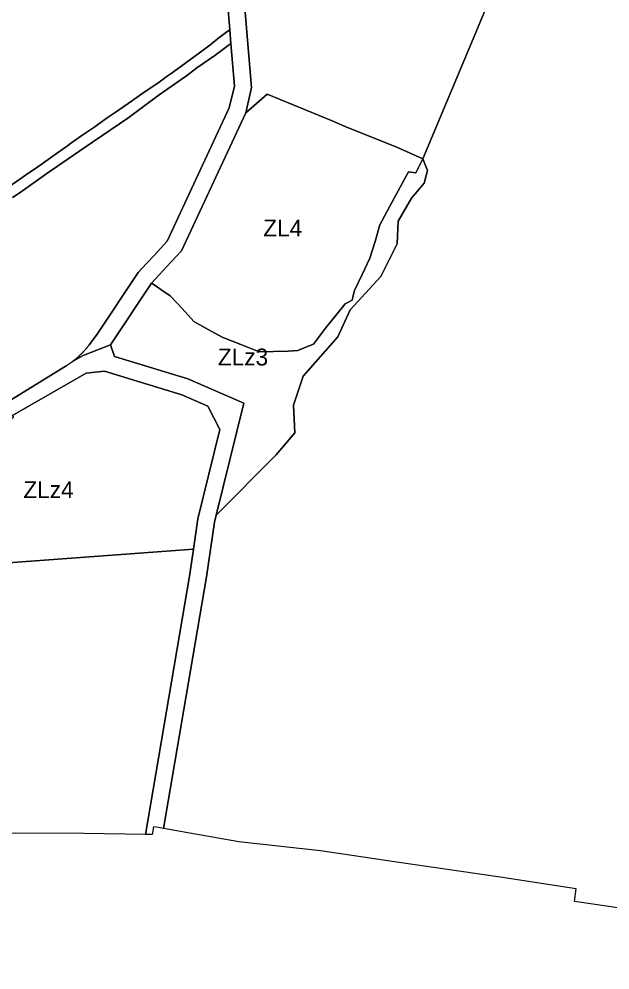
# Model space of a CAD drawing. Extents: x 7439486 to 7443435, y 5551288 to 5554556.
# Drawn here: x 7441389 to 7441738, y 5552052 to 5552613 of the extents above; entities that cross this region are included whole.
import ezdxf

# ---------------------------------------------------------------- set-up
doc = ezdxf.new("R2010")
doc.units = 0
doc.layers.add('linie_rozgraniczajace', color=7, linetype='Continuous')
doc.layers.add('oznaczenia_przeznaczen', color=7, linetype='Continuous')

msp = doc.modelspace()

# ---------------------------------------------------------------- linework, layer by layer
at = {"layer": 'linie_rozgraniczajace'}
for points in [[(7441632.49, 5552909.09), (7441605.42, 5552850.4), (7441542.65, 5552745.21), (7441531.72, 5552727.75), (7441527.41, 5552715.36), (7441523.69, 5552674.78), (7441520.39, 5552638.69), (7441525.97, 5552572.89), (7441522.44, 5552558.06), (7441484.47, 5552476.5), (7441475.68, 5552466.97), (7441471.28, 5552462.21), (7441466.88, 5552457.45)], [(7441473.89, 5552135.18), (7441499.22, 5552283.92), (7441504.07, 5552316.14), (7441505.1, 5552320.35), (7441540.55, 5552355.88), (7441551.52, 5552368.86), (7441550.62, 5552385.33), (7441556.44, 5552402.45), (7441576.8, 5552425.65), (7441584.14, 5552441.59), (7441602.31, 5552461.23), (7441611.94, 5552480.61), (7441612.56, 5552494.07), (7441620.35, 5552507.59), (7441627.86, 5552516.46), (7441629.87, 5552523.95), (7441627.21, 5552530.83), (7441656.87, 5552601.68), (7441668.96, 5552630.65), (7441733.17, 5552791.22), (7441747.99, 5552826)], [(7441510.43, 5552637.85), (7441513.04, 5552607.04), (7441510.55, 5552605.2), (7441505.84, 5552601.59), (7441504.12, 5552600.32), (7441500.41, 5552597.45), (7441495.18, 5552593.48), (7441481.86, 5552583.7), (7441478.5, 5552581.3), (7441476.09, 5552579.58), (7441471.38, 5552576.08), (7441464.62, 5552571.59), (7441462.49, 5552570.18), (7441459.66, 5552568.19), (7441458.28, 5552567.21), (7441453.05, 5552563.53), (7441445.23, 5552558.12), (7441440.65, 5552554.95), (7441435.59, 5552551.46), (7441433.36, 5552549.75), (7441425.64, 5552544.5), (7441418.94, 5552539.84), (7441417.08, 5552538.48), (7441411.15, 5552534.38), (7441401.65, 5552527.52), (7441397.62, 5552524.73), (7441393.74, 5552522.05), (7441389.56, 5552519.16), (7441381.95, 5552513.91)], [(7441420.23, 5552411.17), (7441420.58, 5552411.44), (7441420.94, 5552411.71), (7441421.29, 5552411.99), (7441421.64, 5552412.27), (7441421.98, 5552412.55), (7441422.32, 5552412.84), (7441422.67, 5552413.13), (7441423, 5552413.42), (7441423.34, 5552413.72), (7441423.67, 5552414.02), (7441424, 5552414.32), (7441424.33, 5552414.62), (7441424.66, 5552414.93), (7441424.98, 5552415.24), (7441425.3, 5552415.55), (7441425.61, 5552415.87), (7441425.93, 5552416.19), (7441426.24, 5552416.51), (7441426.55, 5552416.83), (7441426.85, 5552417.16), (7441427.15, 5552417.49), (7441427.45, 5552417.82), (7441427.75, 5552418.16), (7441428.04, 5552418.49), (7441428.33, 5552418.83), (7441428.62, 5552419.18), (7441428.9, 5552419.52), (7441429.18, 5552419.87), (7441429.46, 5552420.22), (7441429.73, 5552420.57), (7441430.01, 5552420.93), (7441430.04, 5552420.98), (7441434.31, 5552426.64), (7441459, 5552463.65), (7441463.93, 5552469), (7441468.33, 5552473.76), (7441476.07, 5552482.13), (7441512.75, 5552560.95), (7441515.88, 5552573.67), (7441513.73, 5552598.95), (7441513.04, 5552607.04), (7441510.43, 5552637.85)], [(7441668.96, 5552630.65), (7441656.87, 5552601.68), (7441627.21, 5552530.83), (7441612.07, 5552537.47), (7441581.21, 5552549.95), (7441573.64, 5552553.26), (7441535.21, 5552569.06), (7441528.82, 5552563.56), (7441522.44, 5552558.06), (7441525.97, 5552572.89), (7441520.39, 5552638.69)], [(7441381.95, 5552513.91), (7441389.56, 5552519.16), (7441393.74, 5552522.05), (7441397.62, 5552524.73), (7441401.65, 5552527.52), (7441411.15, 5552534.38), (7441417.08, 5552538.48), (7441418.94, 5552539.84), (7441425.64, 5552544.5), (7441433.36, 5552549.75), (7441435.59, 5552551.46), (7441440.65, 5552554.95), (7441445.23, 5552558.12), (7441453.05, 5552563.53), (7441458.28, 5552567.21), (7441459.66, 5552568.19), (7441462.49, 5552570.18), (7441464.62, 5552571.59), (7441471.38, 5552576.08), (7441476.09, 5552579.58), (7441478.5, 5552581.3), (7441481.86, 5552583.7), (7441495.18, 5552593.48), (7441500.41, 5552597.45), (7441504.12, 5552600.32), (7441505.84, 5552601.59), (7441510.55, 5552605.2), (7441513.04, 5552607.04), (7441513.73, 5552598.95), (7441511.38, 5552597.2), (7441504.22, 5552591.85), (7441493.64, 5552584.47), (7441487.5, 5552579.76), (7441471.35, 5552568.59), (7441452.72, 5552554.9), (7441427.05, 5552537.31), (7441404.95, 5552522.05), (7441389.11, 5552510.97), (7441384.56, 5552507.91)], [(7441384.56, 5552507.91), (7441389.11, 5552510.97), (7441404.95, 5552522.05), (7441427.05, 5552537.31), (7441452.72, 5552554.9), (7441471.35, 5552568.59), (7441487.5, 5552579.76), (7441493.64, 5552584.47), (7441504.22, 5552591.85), (7441511.38, 5552597.2), (7441513.73, 5552598.95), (7441515.88, 5552573.67), (7441512.75, 5552560.95)], [(7441512.75, 5552560.95), (7441476.07, 5552482.13), (7441468.33, 5552473.76), (7441463.93, 5552469), (7441459, 5552463.65), (7441434.31, 5552426.64), (7441430.04, 5552420.98), (7441430.01, 5552420.93), (7441429.73, 5552420.57), (7441429.46, 5552420.22), (7441429.18, 5552419.87), (7441428.9, 5552419.52), (7441428.62, 5552419.18), (7441428.33, 5552418.83), (7441428.04, 5552418.49), (7441427.75, 5552418.16), (7441427.45, 5552417.82), (7441427.15, 5552417.49), (7441426.85, 5552417.16), (7441426.55, 5552416.83), (7441426.24, 5552416.51), (7441425.93, 5552416.19), (7441425.61, 5552415.87), (7441425.3, 5552415.55), (7441424.98, 5552415.24), (7441424.66, 5552414.93), (7441424.33, 5552414.62), (7441424, 5552414.32), (7441423.67, 5552414.02), (7441423.34, 5552413.72), (7441423, 5552413.42), (7441422.67, 5552413.13), (7441422.32, 5552412.84), (7441421.98, 5552412.55), (7441421.64, 5552412.27), (7441421.29, 5552411.99), (7441420.94, 5552411.71), (7441420.58, 5552411.44), (7441420.23, 5552411.17), (7441420.05, 5552411.04), (7441419.7, 5552410.77), (7441419.33, 5552410.51), (7441418.97, 5552410.25), (7441418.6, 5552409.99), (7441418.23, 5552409.74), (7441417.86, 5552409.49), (7441417.49, 5552409.25), (7441417.11, 5552409), (7441416.74, 5552408.76), (7441416.36, 5552408.53), (7441359.09, 5552373.26)], [(7441466.88, 5552457.45), (7441442.47, 5552420.84), (7441426.33, 5552414.67), (7441420.57, 5552411.36), (7441420.23, 5552411.17)], [(7441359.09, 5552373.26), (7441416.36, 5552408.53), (7441416.74, 5552408.76), (7441417.11, 5552409), (7441417.49, 5552409.25), (7441417.86, 5552409.49), (7441418.23, 5552409.74), (7441418.6, 5552409.99), (7441418.97, 5552410.25), (7441419.33, 5552410.51), (7441419.7, 5552410.77), (7441420.05, 5552411.04), (7441420.23, 5552411.17), (7441420.57, 5552411.36), (7441426.33, 5552414.67), (7441442.47, 5552420.84), (7441444.89, 5552414.09), (7441488.24, 5552400.83), (7441521.36, 5552386.38), (7441505.1, 5552320.35), (7441504.07, 5552316.14), (7441499.22, 5552283.92), (7441473.89, 5552135.18), (7441470.85, 5552135.71), (7441468.04, 5552136.23), (7441467.27, 5552131.65), (7441463.15, 5552131.7), (7441489.35, 5552285.5), (7441491.57, 5552300.28), (7441494.25, 5552318.09), (7441507.26, 5552370.92), (7441500, 5552384.79), (7441484.76, 5552391.43), (7441439.09, 5552405.41), (7441428.13, 5552404.2), (7441384.35, 5552379.06)], [(7442096.7, 5552051.64), (7442052.41, 5552058.69), (7442007.9, 5552065.63), (7441974.28, 5552069.63), (7441970.71, 5552070.24), (7441968.39, 5552055.18), (7441719.51, 5552091.77), (7441716.76, 5552092.12), (7441717.74, 5552099.65), (7441672.76, 5552106.41), (7441610.34, 5552115.55), (7441566.6, 5552122), (7441518.49, 5552127.39), (7441473.89, 5552135.18)]]:
    msp.add_lwpolyline(points, dxfattribs=at)
for points in [[(7441466.88, 5552457.45), (7441471.28, 5552462.21), (7441475.68, 5552466.97), (7441484.47, 5552476.5), (7441522.44, 5552558.06), (7441528.82, 5552563.56), (7441535.21, 5552569.06), (7441573.64, 5552553.26), (7441581.21, 5552549.95), (7441612.07, 5552537.47), (7441627.21, 5552530.83), (7441622.94, 5552522.46), (7441618.61, 5552523.16), (7441610.21, 5552507.5), (7441601.81, 5552491.83), (7441598.86, 5552481.97), (7441595.9, 5552472.11), (7441591.29, 5552462.52), (7441586.68, 5552452.94), (7441586.01, 5552450.12), (7441585.34, 5552447.3), (7441581.24, 5552445.23), (7441575.45, 5552438.02), (7441569.67, 5552430.81), (7441562.46, 5552421.41), (7441557.89, 5552419.53), (7441553.33, 5552417.65), (7441550.45, 5552417.37), (7441547.58, 5552417.1), (7441538.98, 5552416.91), (7441530.38, 5552416.72), (7441519.51, 5552421.07), (7441508.64, 5552425.42), (7441500.27, 5552430.08), (7441491.89, 5552434.74), (7441484.83, 5552442.32), (7441477.78, 5552449.9), (7441472.33, 5552453.67), (7441468.99, 5552455.99)], [(7441442.47, 5552420.84), (7441466.88, 5552457.45), (7441468.99, 5552455.99), (7441472.33, 5552453.67), (7441477.78, 5552449.9), (7441484.83, 5552442.32), (7441491.89, 5552434.74), (7441500.27, 5552430.08), (7441508.64, 5552425.42), (7441519.51, 5552421.07), (7441530.38, 5552416.72), (7441538.98, 5552416.91), (7441547.58, 5552417.1), (7441550.45, 5552417.37), (7441553.33, 5552417.65), (7441557.89, 5552419.53), (7441562.46, 5552421.41), (7441569.67, 5552430.81), (7441575.45, 5552438.02), (7441581.24, 5552445.23), (7441585.34, 5552447.3), (7441586.01, 5552450.12), (7441586.68, 5552452.94), (7441591.29, 5552462.52), (7441595.9, 5552472.11), (7441598.86, 5552481.97), (7441601.81, 5552491.83), (7441610.21, 5552507.5), (7441618.61, 5552523.16), (7441622.94, 5552522.46), (7441627.21, 5552530.83), (7441629.87, 5552523.95), (7441627.86, 5552516.46), (7441620.35, 5552507.59), (7441612.56, 5552494.07), (7441611.94, 5552480.61), (7441602.31, 5552461.23), (7441584.14, 5552441.59), (7441576.8, 5552425.65), (7441556.44, 5552402.45), (7441550.62, 5552385.33), (7441551.52, 5552368.86), (7441540.55, 5552355.88), (7441505.1, 5552320.35), (7441521.36, 5552386.38), (7441488.24, 5552400.83), (7441444.89, 5552414.09)], [(7441250.49, 5552286.2), (7441259.42, 5552309.8), (7441277.55, 5552320.56), (7441332.2, 5552313.39), (7441360.9, 5552309.63), (7441363.5, 5552318.05), (7441366.11, 5552326.46), (7441372.81, 5552346.59), (7441379.51, 5552366.72), (7441381.89, 5552374.63), (7441385.51, 5552378.41), (7441384.35, 5552379.06), (7441428.13, 5552404.2), (7441439.09, 5552405.41), (7441484.76, 5552391.43), (7441500, 5552384.79), (7441507.26, 5552370.92), (7441494.25, 5552318.09), (7441491.57, 5552300.28), (7441347.17, 5552289.52), (7441333.01, 5552281.15)], [(7441163.12, 5552132.05), (7441166.55, 5552167.87), (7441170.21, 5552188.26), (7441174, 5552196.22), (7441177.95, 5552204.48), (7441191.9, 5552225.82), (7441202.03, 5552238.56), (7441223.94, 5552294.61), (7441225.43, 5552290.48), (7441250.49, 5552286.2), (7441333.01, 5552281.15), (7441347.17, 5552289.52), (7441491.57, 5552300.28), (7441489.35, 5552285.5), (7441463.15, 5552131.7), (7441427.01, 5552132.17), (7441386.44, 5552132.52), (7441339.55, 5552132.31), (7441336.65, 5552132.29), (7441248.59, 5552132.51), (7441204.07, 5552132.42)]]:
    msp.add_lwpolyline(points, close=True, dxfattribs=at)

# ---------------------------------------------------------------- texts
at = {"layer": 'oznaczenia_przeznaczen'}
for s, p in [('ZL4', (7441532.81, 5552484.92)), ('ZLz3', (7441505.99, 5552408.72)), ('ZLz4', (7441391.07, 5552330.35))]:
    msp.add_text(s, height=10, dxfattribs=at).set_placement(p)

doc.saveas('drawing.dxf')
